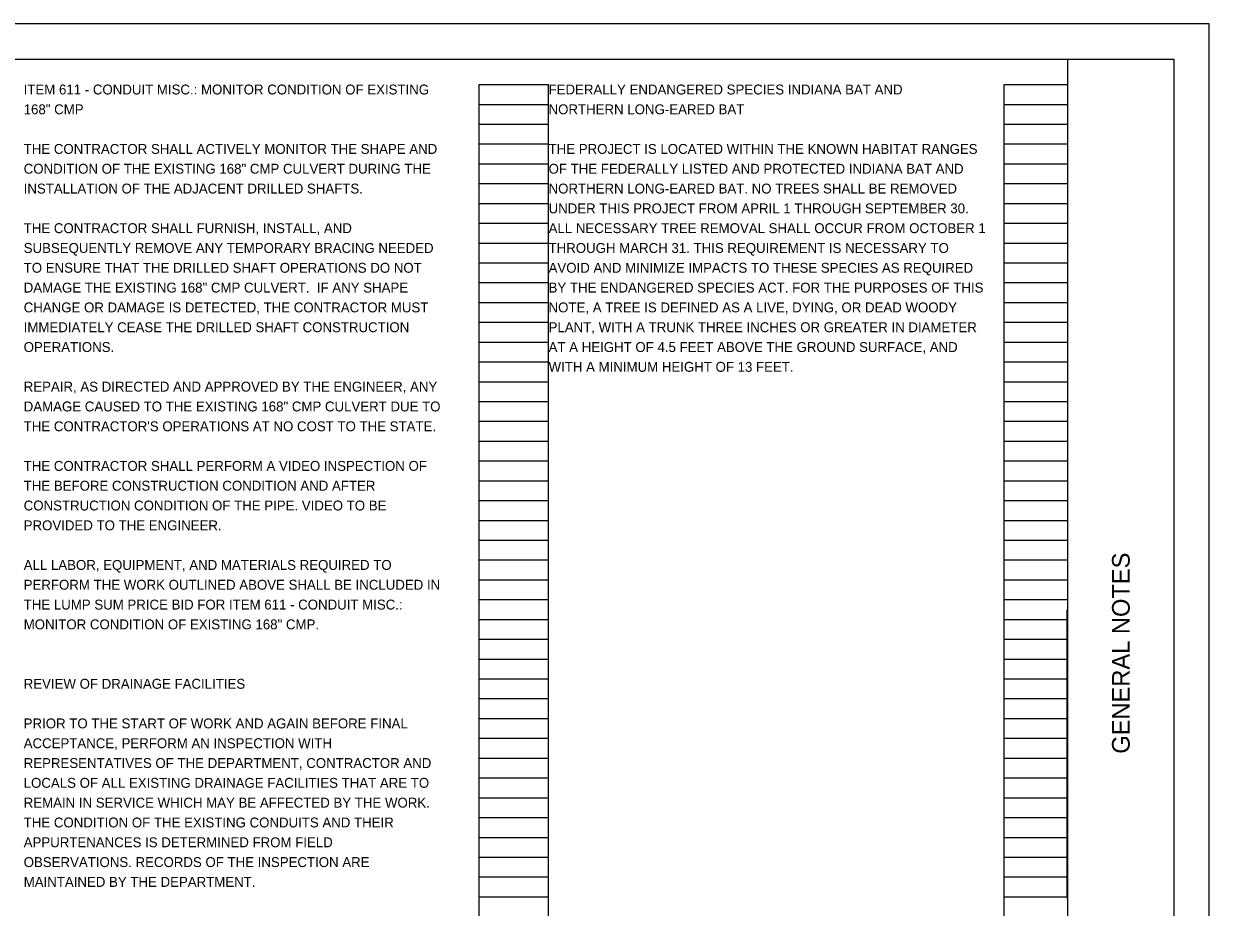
# Model space of a CAD drawing. Extents: x 0 to 34, y 0 to 22.
# Drawn here: x 17.24 to 34, y 9.51 to 22 of the extents above; entities that cross this region are included whole.
import ezdxf

# ---------------------------------------------------------------- set-up
doc = ezdxf.new("R2010")
doc.units = 0
for name, color, linetype in [('Default', 7, 'Continuous'), ('SH_Border', 7, 'Continuous'), ('SH_Cut_Line', 7, 'Continuous'), ('SH_Data', 7, 'Continuous'), ('SH_Text', 7, 'Continuous')]:
    doc.layers.add(name, color=color, linetype=linetype)

msp = doc.modelspace()

# ---------------------------------------------------------------- linework, layer by layer
at = {"layer": 'Default'}
msp.add_line((31.989, 9.641), (31.989, 13.717), dxfattribs=at)
at = {"layer": 'SH_Border'}
msp.add_line((32, 0.5), (32, 21.5), dxfattribs=at)
msp.add_lwpolyline([(1.5, 21.5), (33.5, 21.5), (33.5, 0.5), (1.5, 0.5)], close=True, dxfattribs=at)
at = {"layer": 'SH_Cut_Line'}
msp.add_lwpolyline([(0, 0), (34, 0), (34, 22), (0, 22)], close=True, dxfattribs=at)
at = {"layer": 'SH_Data'}
for p, q in [((23.68, 0.98), (23.68, 21.14)), ((23.68, 21.14), (24.66, 21.14)), ((24.66, 0.98), (24.66, 21.14)), ((31.1, 0.98), (31.1, 21.14)), ((31.1, 21.14), (32, 21.14)), ((32, 0.98), (32, 21.14)), ((23.68, 20.86), (24.66, 20.86)), ((31.1, 20.86), (32, 20.86)), ((23.68, 20.58), (24.66, 20.58)), ((31.1, 20.58), (32, 20.58)), ((23.68, 20.3), (24.66, 20.3)), ((31.1, 20.3), (32, 20.3)), ((23.68, 20.02), (24.66, 20.02)), ((31.1, 20.02), (32, 20.02)), ((23.68, 19.74), (24.66, 19.74)), ((31.1, 19.74), (32, 19.74)), ((23.68, 19.46), (24.66, 19.46)), ((31.1, 19.46), (32, 19.46)), ((23.68, 19.18), (24.66, 19.18)), ((31.1, 19.18), (32, 19.18)), ((23.68, 18.9), (24.66, 18.9)), ((31.1, 18.9), (32, 18.9)), ((23.68, 18.62), (24.66, 18.62)), ((31.1, 18.62), (32, 18.62)), ((23.68, 18.34), (24.66, 18.34)), ((31.1, 18.34), (32, 18.34)), ((23.68, 18.06), (24.66, 18.06)), ((31.1, 18.06), (32, 18.06)), ((23.68, 17.78), (24.66, 17.78)), ((31.1, 17.78), (32, 17.78)), ((23.68, 17.5), (24.66, 17.5)), ((31.1, 17.5), (32, 17.5)), ((23.68, 17.22), (24.66, 17.22)), ((31.1, 17.22), (32, 17.22)), ((23.68, 16.94), (24.66, 16.94)), ((31.1, 16.94), (32, 16.94)), ((23.68, 16.66), (24.66, 16.66)), ((31.1, 16.66), (32, 16.66)), ((23.68, 16.38), (24.66, 16.38)), ((31.1, 16.38), (32, 16.38)), ((23.68, 16.1), (24.66, 16.1)), ((31.1, 16.1), (32, 16.1)), ((23.68, 15.82), (24.66, 15.82)), ((31.1, 15.82), (32, 15.82)), ((23.68, 15.54), (24.66, 15.54)), ((31.1, 15.54), (32, 15.54)), ((23.68, 15.26), (24.66, 15.26)), ((31.1, 15.26), (32, 15.26)), ((23.68, 14.98), (24.66, 14.98)), ((31.1, 14.98), (32, 14.98)), ((23.68, 14.7), (24.66, 14.7)), ((31.1, 14.7), (32, 14.7)), ((23.68, 14.42), (24.66, 14.42)), ((31.1, 14.42), (32, 14.42)), ((23.68, 14.14), (24.66, 14.14)), ((31.1, 14.14), (32, 14.14)), ((23.68, 13.86), (24.66, 13.86)), ((31.1, 13.86), (32, 13.86)), ((23.68, 13.58), (24.66, 13.58)), ((31.1, 13.58), (32, 13.58)), ((23.68, 13.3), (24.66, 13.3)), ((31.1, 13.3), (32, 13.3)), ((23.68, 13.02), (24.66, 13.02)), ((31.1, 13.02), (32, 13.02)), ((23.68, 12.74), (24.66, 12.74)), ((31.1, 12.74), (32, 12.74)), ((23.68, 12.46), (24.66, 12.46)), ((31.1, 12.46), (32, 12.46)), ((23.68, 12.18), (24.66, 12.18)), ((31.1, 12.18), (32, 12.18)), ((23.68, 11.9), (24.66, 11.9)), ((31.1, 11.9), (32, 11.9)), ((23.68, 11.62), (24.66, 11.62)), ((31.1, 11.62), (32, 11.62)), ((23.68, 11.34), (24.66, 11.34)), ((31.1, 11.34), (32, 11.34)), ((23.68, 11.06), (24.66, 11.06)), ((31.1, 11.06), (32, 11.06)), ((23.68, 10.78), (24.66, 10.78)), ((31.1, 10.78), (32, 10.78)), ((23.68, 10.5), (24.66, 10.5)), ((31.1, 10.5), (32, 10.5)), ((23.68, 10.22), (24.66, 10.22)), ((31.1, 10.22), (32, 10.22)), ((23.68, 9.94), (24.66, 9.94)), ((31.1, 9.94), (32, 9.94)), ((23.68, 9.66), (24.66, 9.66)), ((31.1, 9.66), (32, 9.66))]:
    msp.add_line(p, q, dxfattribs=at)

# ---------------------------------------------------------------- texts
msp.add_text('GENERAL NOTES', height=0.25, rotation=90, dxfattribs=at).set_placement((32.875, 11.682))
at = {"layer": 'SH_Text'}
for s, p in [('ITEM 611 - CONDUIT MISC.: MONITOR CONDITION OF EXISTING ', (17.24, 21)), ('FEDERALLY ENDANGERED SPECIES INDIANA BAT AND ', (24.66, 21)), ('168" CMP', (17.24, 20.72)), ('NORTHERN LONG-EARED BAT', (24.66, 20.72)), ('THE CONTRACTOR SHALL ACTIVELY MONITOR THE SHAPE AND ', (17.24, 20.16)), ('THE PROJECT IS LOCATED WITHIN THE KNOWN HABITAT RANGES ', (24.66, 20.16)), ('CONDITION OF THE EXISTING 168" CMP CULVERT DURING THE ', (17.24, 19.88)), ('OF THE FEDERALLY LISTED AND PROTECTED INDIANA BAT AND ', (24.66, 19.88)), ('INSTALLATION OF THE ADJACENT DRILLED SHAFTS.', (17.24, 19.6)), ('NORTHERN LONG-EARED BAT. NO TREES SHALL BE REMOVED ', (24.66, 19.6)), ('UNDER THIS PROJECT FROM APRIL 1 THROUGH SEPTEMBER 30. ', (24.66, 19.32)), ('THE CONTRACTOR SHALL FURNISH, INSTALL, AND ', (17.24, 19.04)), ('ALL NECESSARY TREE REMOVAL SHALL OCCUR FROM OCTOBER 1 ', (24.66, 19.04)), ('SUBSEQUENTLY REMOVE ANY TEMPORARY BRACING NEEDED ', (17.24, 18.76)), ('THROUGH MARCH 31. THIS REQUIREMENT IS NECESSARY TO ', (24.66, 18.76)), ('TO ENSURE THAT THE DRILLED SHAFT OPERATIONS DO NOT ', (17.24, 18.48)), ('AVOID AND MINIMIZE IMPACTS TO THESE SPECIES AS REQUIRED ', (24.66, 18.48)), ('DAMAGE THE EXISTING 168" CMP CULVERT.  IF ANY SHAPE ', (17.24, 18.2)), ('BY THE ENDANGERED SPECIES ACT. FOR THE PURPOSES OF THIS ', (24.66, 18.2)), ('CHANGE OR DAMAGE IS DETECTED, THE CONTRACTOR MUST ', (17.24, 17.92)), ('NOTE, A TREE IS DEFINED AS A LIVE, DYING, OR DEAD WOODY ', (24.66, 17.92)), ('IMMEDIATELY CEASE THE DRILLED SHAFT CONSTRUCTION ', (17.24, 17.64)), ('PLANT, WITH A TRUNK THREE INCHES OR GREATER IN DIAMETER ', (24.66, 17.64)), ('OPERATIONS. ', (17.24, 17.36)), ('AT A HEIGHT OF 4.5 FEET ABOVE THE GROUND SURFACE, AND ', (24.66, 17.36)), ('WITH A MINIMUM HEIGHT OF 13 FEET.', (24.66, 17.08)), ('REPAIR, AS DIRECTED AND APPROVED BY THE ENGINEER, ANY ', (17.24, 16.8)), ('DAMAGE CAUSED TO THE EXISTING 168" CMP CULVERT DUE TO ', (17.24, 16.52)), ("THE CONTRACTOR'S OPERATIONS AT NO COST TO THE STATE.", (17.24, 16.24)), ('THE CONTRACTOR SHALL PERFORM A VIDEO INSPECTION OF ', (17.24, 15.68)), ('THE BEFORE CONSTRUCTION CONDITION AND AFTER ', (17.24, 15.4)), ('CONSTRUCTION CONDITION OF THE PIPE. VIDEO TO BE ', (17.24, 15.12)), ('PROVIDED TO THE ENGINEER.', (17.24, 14.84)), ('ALL LABOR, EQUIPMENT, AND MATERIALS REQUIRED TO ', (17.24, 14.28)), ('PERFORM THE WORK OUTLINED ABOVE SHALL BE INCLUDED IN ', (17.24, 14)), ('THE LUMP SUM PRICE BID FOR ITEM 611 - CONDUIT MISC.: ', (17.24, 13.72)), ('MONITOR CONDITION OF EXISTING 168" CMP.', (17.24, 13.44)), ('REVIEW OF DRAINAGE FACILITIES', (17.24, 12.6)), ('PRIOR TO THE START OF WORK AND AGAIN BEFORE FINAL ', (17.24, 12.04)), ('ACCEPTANCE, PERFORM AN INSPECTION WITH ', (17.24, 11.76)), ('REPRESENTATIVES OF THE DEPARTMENT, CONTRACTOR AND', (17.24, 11.48)), ('LOCALS OF ALL EXISTING DRAINAGE FACILITIES THAT ARE TO ', (17.24, 11.2)), ('REMAIN IN SERVICE WHICH MAY BE AFFECTED BY THE WORK. ', (17.24, 10.92)), ('THE CONDITION OF THE EXISTING CONDUITS AND THEIR ', (17.24, 10.64)), ('APPURTENANCES IS DETERMINED FROM FIELD', (17.24, 10.36)), ('OBSERVATIONS. RECORDS OF THE INSPECTION ARE ', (17.24, 10.08)), ('MAINTAINED BY THE DEPARTMENT.', (17.24, 9.8))]:
    msp.add_text(s, height=0.14, dxfattribs=at).set_placement(p)

doc.saveas('drawing.dxf')
